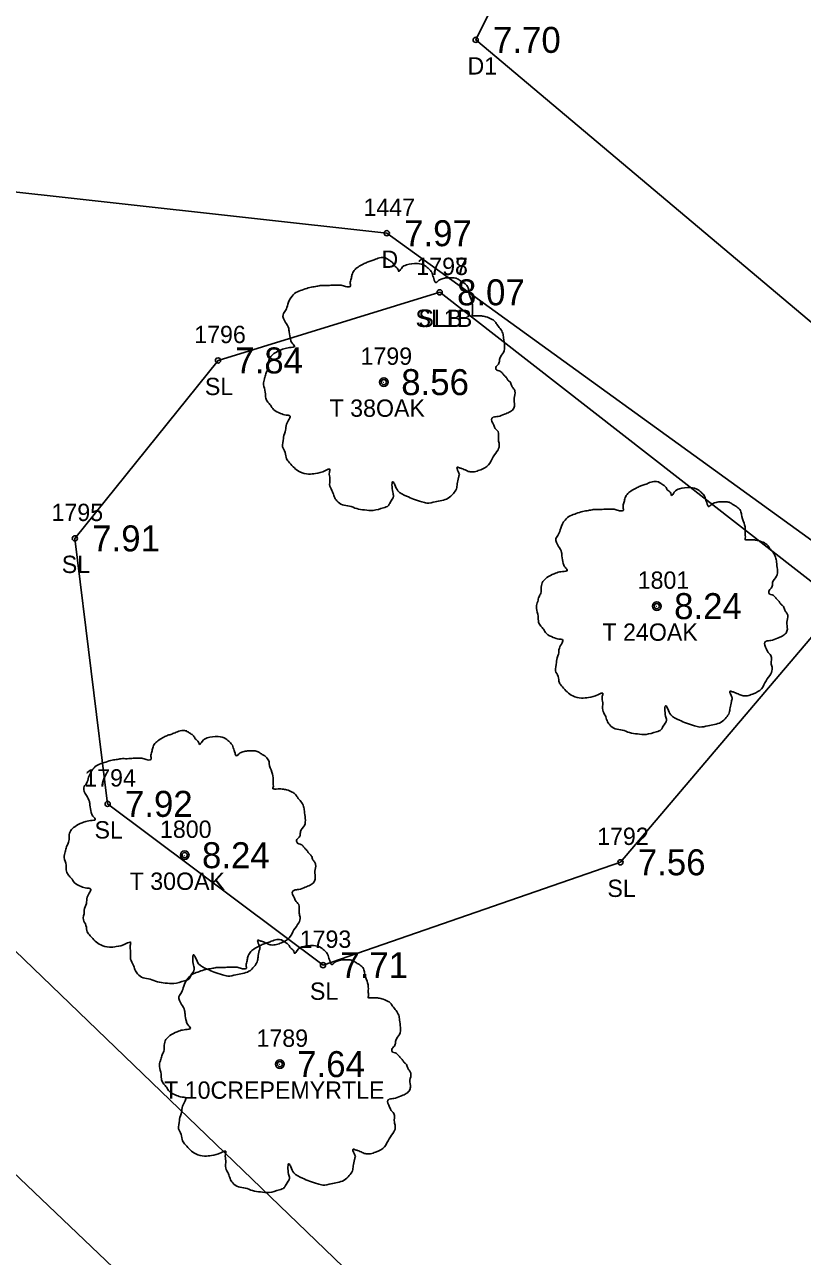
# Model space of a CAD drawing. Extents: x 2608598 to 2610682, y 641451 to 643526.
# Drawn here: x 2609134.2 to 2609179, y 643078.1 to 643149.1 of the extents above; entities that cross this region are included whole.
import ezdxf

# ---------------------------------------------------------------- set-up
doc = ezdxf.new("R2010")
doc.units = 0
for name, color, linetype in [('RD_EX_DR_Pipe', 7, 'Continuous'), ('RD_EX_Driveway', 7, 'Continuous'), ('RD_EX_Driveway_txCode', 7, 'Continuous'), ('RD_EX_Road', 7, 'Continuous'), ('RD_EX_TX_Driveway_ELEV', 7, 'Continuous'), ('RD_EX_TX_VEG_ELEV', 7, 'Continuous'), ('RD_EX_VEG', 7, 'Continuous'), ('RD_EX_VEG_txCode', 7, 'Continuous'), ('RD_SMD_Locator', 7, 'Continuous')]:
    doc.layers.add(name, color=color, linetype=linetype)

msp = doc.modelspace()

# ---------------------------------------------------------------- linework, layer by layer
at = {"layer": 'RD_EX_DR_Pipe'}
msp.add_line((2609069.044, 643157.849), (2609202.653, 643029.203), dxfattribs=at)
at = {"layer": 'RD_EX_Driveway'}
for points in [[(2609166.457, 643161.041), (2609160.17, 643148.257), (2609190.362, 643122.83), (2609213.317, 643102.873), (2609223.768, 643094.8), (2609208.755, 643077.174), (2609183.581, 643050.775)], [(2609100.57, 643145.923), (2609122.94, 643140.66), (2609155.044, 643137.099), (2609182.051, 643117.558), (2609202.041, 643097.354), (2609199.499, 643083.361), (2609176.116, 643060.669)]]:
    msp.add_lwpolyline(points, dxfattribs=at)
at = {"layer": 'RD_EX_Road'}
msp.add_lwpolyline([(2609042.495, 643170.94), (2609058.512, 643155.458), (2609096.06, 643119.372), (2609116.51, 643099.11), (2609162.396, 643055.351), (2609177.209, 643041.342), (2609188.353, 643030.959), (2609199.912, 643019.764), (2609205.803, 643014.044), (2609217.132, 643003.172), (2609235.835, 642983.899), (2609237.032, 642983.51), (2609256.803, 642965.042), (2609258.491, 642962.514), (2609263.653, 642957.664), (2609344.713, 642879.888)], dxfattribs=at)
at = {"layer": 'RD_EX_VEG'}
msp.add_line((2609181.166, 643115.711), (2609158.094, 643133.687), dxfattribs=at)
msp.add_lwpolyline([(2609181.166, 643115.711), (2609168.519, 643100.795), (2609151.366, 643094.858), (2609138.946, 643104.167), (2609137.057, 643119.488), (2609145.31, 643129.756), (2609158.094, 643133.687)], dxfattribs=at)
for centre, radius in [((2609154.878, 643128.504), 0.25), ((2609154.865, 643128.485), 0.0001), ((2609170.613, 643115.578), 0.25), ((2609170.6, 643115.559), 0.0001), ((2609143.388, 643101.204), 0.25), ((2609143.375, 643101.186), 0.0001), ((2609148.877, 643089.147), 0.25), ((2609148.864, 643089.128), 0.0001)]:
    msp.add_circle(centre, radius, dxfattribs=at)
for points in [[(2609155.01, 643135.671), (2609154.71, 643135.696), (2609154.385, 643135.596), (2609154.135, 643135.496), (2609153.91, 643135.421), (2609153.685, 643135.321), (2609153.386, 643135.147), (2609153.161, 643134.946), (2609153.036, 643134.697), (2609152.986, 643134.472), (2609152.936, 643134.197), (2609152.936, 643134.022), (2609152.811, 643133.997), (2609152.661, 643134.022), (2609152.411, 643134.097), (2609152.161, 643134.097), (2609151.911, 643134.097), (2609151.561, 643134.072), (2609151.211, 643134.072), (2609150.937, 643134.022), (2609150.612, 643133.972), (2609150.237, 643133.847), (2609149.887, 643133.722), (2609149.587, 643133.472), (2609149.337, 643132.997), (2609149.212, 643132.648), (2609149.062, 643132.398), (2609149.212, 643131.948), (2609149.387, 643131.598), (2609149.412, 643131.398), (2609149.487, 643130.973), (2609149.587, 643130.748), (2609149.712, 643130.548), (2609149.637, 643130.524), (2609149.262, 643130.473), (2609148.962, 643130.374), (2609148.538, 643130.149), (2609148.313, 643129.924), (2609148.213, 643129.599), (2609148.188, 643129.249), (2609148.088, 643129.049), (2609148.013, 643128.774), (2609147.988, 643128.699), (2609147.938, 643128.374), (2609148.038, 643127.925), (2609148.063, 643127.575), (2609148.188, 643127.35), (2609148.338, 643127.175), (2609148.513, 643126.925), (2609148.912, 643126.7), (2609149.237, 643126.6), (2609149.437, 643126.575), (2609149.262, 643126.075), (2609149.212, 643125.726), (2609149.087, 643125.326), (2609149.087, 643125.251), (2609149.037, 643124.776), (2609149.187, 643124.451), (2609149.262, 643124.076), (2609149.437, 643123.851), (2609149.712, 643123.552), (2609150.037, 643123.327), (2609150.537, 643123.202), (2609150.937, 643123.227), (2609151.511, 643123.402), (2609151.761, 643123.477), (2609151.736, 643123.302), (2609151.761, 643122.927), (2609151.761, 643122.502), (2609151.911, 643122.177), (2609152.011, 643121.902), (2609152.161, 643121.652), (2609152.486, 643121.427), (2609152.886, 643121.353), (2609153.311, 643121.203), (2609153.76, 643121.128), (2609154.26, 643121.103), (2609154.86, 643121.253), (2609155.135, 643121.378), (2609155.235, 643121.552), (2609155.435, 643121.927), (2609155.385, 643122.152), (2609155.41, 643122.752), (2609155.51, 643122.577), (2609155.685, 643122.227), (2609156.184, 643121.927), (2609156.584, 643121.752), (2609157.059, 643121.602), (2609157.359, 643121.527), (2609157.834, 643121.602), (2609158.208, 643121.677), (2609158.583, 643121.802), (2609158.883, 643122.077), (2609159.058, 643122.352), (2609159.108, 643122.627), (2609159.183, 643123.002), (2609159.233, 643123.177)], [(2609159.233, 643123.177), (2609159.158, 643123.352), (2609159.108, 643123.601), (2609159.183, 643123.576), (2609159.358, 643123.527), (2609159.633, 643123.402), (2609159.858, 643123.327), (2609160.183, 643123.352), (2609160.457, 643123.452), (2609160.907, 643123.726), (2609161.182, 643124.201), (2609161.457, 643124.601), (2609161.532, 643124.926), (2609161.482, 643125.151), (2609161.457, 643125.651), (2609161.257, 643125.9), (2609161.207, 643126.025), (2609161.107, 643126.425), (2609161.182, 643126.475), (2609161.457, 643126.525), (2609161.832, 643126.65), (2609162.107, 643126.775), (2609162.332, 643126.95), (2609162.407, 643127.175), (2609162.382, 643127.575), (2609162.432, 643127.975), (2609162.357, 643128.125), (2609162.257, 643128.274), (2609162.182, 643128.474), (2609162.032, 643128.624), (2609161.932, 643128.774), (2609161.832, 643128.874), (2609161.707, 643129.024), (2609161.532, 643129.149), (2609161.382, 643129.199), (2609161.332, 643129.349), (2609161.482, 643129.549), (2609161.532, 643129.649), (2609161.557, 643129.874), (2609161.782, 643130.224), (2609161.832, 643130.623), (2609161.782, 643131.048), (2609161.732, 643131.323), (2609161.582, 643131.598), (2609161.382, 643131.848), (2609161.257, 643132.023), (2609161.082, 643132.148), (2609160.757, 643132.273), (2609160.507, 643132.323), (2609160.158, 643132.323), (2609159.958, 643132.373), (2609159.983, 643132.423), (2609159.983, 643132.573), (2609159.983, 643132.848), (2609159.908, 643133.297), (2609159.758, 643133.797), (2609159.758, 643133.822), (2609159.658, 643134.072), (2609159.433, 643134.272), (2609159.258, 643134.372), (2609159.058, 643134.497), (2609158.808, 643134.522), (2609158.508, 643134.522), (2609158.233, 643134.472), (2609158.033, 643134.372), (2609157.859, 643134.247), (2609157.784, 643134.397), (2609157.684, 643134.697), (2609157.634, 643134.847), (2609157.484, 643135.022), (2609157.259, 643135.221), (2609156.809, 643135.346), (2609156.184, 643135.271), (2609155.884, 643135.071), (2609155.734, 643134.897), (2609155.685, 643135.022), (2609155.485, 643135.221), (2609155.385, 643135.396), (2609155.21, 643135.521), (2609155.06, 643135.621), (2609154.96, 643135.671)], [(2609170.745, 643122.745), (2609170.445, 643122.77), (2609170.12, 643122.67), (2609169.87, 643122.57), (2609169.645, 643122.495), (2609169.42, 643122.395), (2609169.121, 643122.221), (2609168.896, 643122.021), (2609168.771, 643121.771), (2609168.721, 643121.546), (2609168.671, 643121.271), (2609168.671, 643121.096), (2609168.546, 643121.071), (2609168.396, 643121.096), (2609168.146, 643121.171), (2609167.896, 643121.171), (2609167.646, 643121.171), (2609167.296, 643121.146), (2609166.946, 643121.146), (2609166.672, 643121.096), (2609166.347, 643121.046), (2609165.972, 643120.921), (2609165.622, 643120.796), (2609165.322, 643120.546), (2609165.072, 643120.072), (2609164.947, 643119.722), (2609164.797, 643119.472), (2609164.947, 643119.022), (2609165.122, 643118.672), (2609165.147, 643118.472), (2609165.222, 643118.047), (2609165.322, 643117.823), (2609165.447, 643117.623), (2609165.372, 643117.598), (2609164.997, 643117.548), (2609164.697, 643117.448), (2609164.273, 643117.223), (2609164.048, 643116.998), (2609163.948, 643116.673), (2609163.923, 643116.323), (2609163.823, 643116.123), (2609163.748, 643115.848), (2609163.723, 643115.773), (2609163.673, 643115.449), (2609163.773, 643114.999), (2609163.798, 643114.649), (2609163.923, 643114.424), (2609164.073, 643114.249), (2609164.248, 643113.999), (2609164.647, 643113.774), (2609164.972, 643113.674), (2609165.172, 643113.649), (2609164.997, 643113.15), (2609164.947, 643112.8), (2609164.822, 643112.4), (2609164.822, 643112.325), (2609164.772, 643111.85), (2609164.922, 643111.525), (2609164.997, 643111.15), (2609165.172, 643110.926), (2609165.447, 643110.626), (2609165.772, 643110.401), (2609166.272, 643110.276), (2609166.672, 643110.301), (2609167.246, 643110.476), (2609167.496, 643110.551), (2609167.471, 643110.376), (2609167.496, 643110.001), (2609167.496, 643109.576), (2609167.646, 643109.251), (2609167.746, 643108.976), (2609167.896, 643108.726), (2609168.221, 643108.502), (2609168.621, 643108.427), (2609169.046, 643108.277), (2609169.495, 643108.202), (2609169.995, 643108.177), (2609170.595, 643108.327), (2609170.87, 643108.452), (2609170.97, 643108.627), (2609171.17, 643109.001), (2609171.12, 643109.226), (2609171.145, 643109.826), (2609171.245, 643109.651), (2609171.42, 643109.301), (2609171.919, 643109.001), (2609172.319, 643108.826), (2609172.794, 643108.676), (2609173.094, 643108.602), (2609173.569, 643108.676), (2609173.943, 643108.751), (2609174.318, 643108.876), (2609174.618, 643109.151), (2609174.793, 643109.426), (2609174.843, 643109.701), (2609174.918, 643110.076), (2609174.968, 643110.251)], [(2609174.968, 643110.251), (2609174.893, 643110.426), (2609174.843, 643110.676), (2609174.918, 643110.651), (2609175.093, 643110.601), (2609175.368, 643110.476), (2609175.593, 643110.401), (2609175.918, 643110.426), (2609176.192, 643110.526), (2609176.642, 643110.801), (2609176.917, 643111.275), (2609177.192, 643111.675), (2609177.267, 643112), (2609177.217, 643112.225), (2609177.192, 643112.725), (2609176.992, 643112.975), (2609176.942, 643113.1), (2609176.842, 643113.499), (2609176.917, 643113.549), (2609177.192, 643113.599), (2609177.567, 643113.724), (2609177.842, 643113.849), (2609178.067, 643114.024), (2609178.142, 643114.249), (2609178.117, 643114.649), (2609178.167, 643115.049), (2609178.092, 643115.199), (2609177.992, 643115.349), (2609177.917, 643115.549), (2609177.767, 643115.698), (2609177.667, 643115.848), (2609177.567, 643115.948), (2609177.442, 643116.098), (2609177.267, 643116.223), (2609177.117, 643116.273), (2609177.067, 643116.423), (2609177.217, 643116.623), (2609177.267, 643116.723), (2609177.292, 643116.948), (2609177.517, 643117.298), (2609177.567, 643117.698), (2609177.517, 643118.122), (2609177.467, 643118.397), (2609177.317, 643118.672), (2609177.117, 643118.922), (2609176.992, 643119.097), (2609176.817, 643119.222), (2609176.492, 643119.347), (2609176.242, 643119.397), (2609175.893, 643119.397), (2609175.693, 643119.447), (2609175.718, 643119.497), (2609175.718, 643119.647), (2609175.718, 643119.922), (2609175.643, 643120.371), (2609175.493, 643120.871), (2609175.493, 643120.896), (2609175.393, 643121.146), (2609175.168, 643121.346), (2609174.993, 643121.446), (2609174.793, 643121.571), (2609174.543, 643121.596), (2609174.243, 643121.596), (2609173.968, 643121.546), (2609173.768, 643121.446), (2609173.594, 643121.321), (2609173.519, 643121.471), (2609173.419, 643121.771), (2609173.369, 643121.921), (2609173.219, 643122.096), (2609172.994, 643122.296), (2609172.544, 643122.42), (2609171.919, 643122.346), (2609171.619, 643122.146), (2609171.469, 643121.971), (2609171.42, 643122.096), (2609171.22, 643122.296), (2609171.12, 643122.47), (2609170.945, 643122.595), (2609170.795, 643122.695), (2609170.695, 643122.745)], [(2609143.52, 643108.372), (2609143.22, 643108.397), (2609142.895, 643108.297), (2609142.645, 643108.197), (2609142.42, 643108.122), (2609142.195, 643108.022), (2609141.896, 643107.847), (2609141.671, 643107.647), (2609141.546, 643107.397), (2609141.496, 643107.172), (2609141.446, 643106.897), (2609141.446, 643106.722), (2609141.321, 643106.697), (2609141.171, 643106.722), (2609140.921, 643106.797), (2609140.671, 643106.797), (2609140.421, 643106.797), (2609140.071, 643106.772), (2609139.722, 643106.772), (2609139.447, 643106.722), (2609139.122, 643106.672), (2609138.747, 643106.547), (2609138.397, 643106.422), (2609138.097, 643106.173), (2609137.847, 643105.698), (2609137.722, 643105.348), (2609137.573, 643105.098), (2609137.722, 643104.648), (2609137.897, 643104.298), (2609137.922, 643104.098), (2609137.997, 643103.674), (2609138.097, 643103.449), (2609138.222, 643103.249), (2609138.147, 643103.224), (2609137.772, 643103.174), (2609137.473, 643103.074), (2609137.048, 643102.849), (2609136.823, 643102.624), (2609136.723, 643102.299), (2609136.698, 643101.949), (2609136.598, 643101.75), (2609136.523, 643101.475), (2609136.498, 643101.4), (2609136.448, 643101.075), (2609136.548, 643100.625), (2609136.573, 643100.275), (2609136.698, 643100.05), (2609136.848, 643099.875), (2609137.023, 643099.625), (2609137.423, 643099.401), (2609137.747, 643099.301), (2609137.947, 643099.276), (2609137.772, 643098.776), (2609137.722, 643098.426), (2609137.598, 643098.026), (2609137.598, 643097.951), (2609137.548, 643097.476), (2609137.697, 643097.151), (2609137.772, 643096.777), (2609137.947, 643096.552), (2609138.222, 643096.252), (2609138.547, 643096.027), (2609139.047, 643095.902), (2609139.447, 643095.927), (2609140.021, 643096.102), (2609140.271, 643096.177), (2609140.246, 643096.002), (2609140.271, 643095.627), (2609140.271, 643095.202), (2609140.421, 643094.878), (2609140.521, 643094.603), (2609140.671, 643094.353), (2609140.996, 643094.128), (2609141.396, 643094.053), (2609141.821, 643093.903), (2609142.271, 643093.828), (2609142.77, 643093.803), (2609143.37, 643093.953), (2609143.645, 643094.078), (2609143.745, 643094.253), (2609143.945, 643094.628), (2609143.895, 643094.853), (2609143.92, 643095.452), (2609144.02, 643095.277), (2609144.195, 643094.927), (2609144.694, 643094.628), (2609145.094, 643094.453), (2609145.569, 643094.303), (2609145.869, 643094.228), (2609146.344, 643094.303), (2609146.719, 643094.378), (2609147.093, 643094.503), (2609147.393, 643094.778), (2609147.568, 643095.052), (2609147.618, 643095.327), (2609147.693, 643095.702), (2609147.743, 643095.877)], [(2609147.743, 643095.877), (2609147.668, 643096.052), (2609147.618, 643096.302), (2609147.693, 643096.277), (2609147.868, 643096.227), (2609148.143, 643096.102), (2609148.368, 643096.027), (2609148.693, 643096.052), (2609148.968, 643096.152), (2609149.417, 643096.427), (2609149.692, 643096.902), (2609149.967, 643097.301), (2609150.042, 643097.626), (2609149.992, 643097.851), (2609149.967, 643098.351), (2609149.767, 643098.601), (2609149.717, 643098.726), (2609149.617, 643099.126), (2609149.692, 643099.176), (2609149.967, 643099.226), (2609150.342, 643099.351), (2609150.617, 643099.475), (2609150.842, 643099.65), (2609150.917, 643099.875), (2609150.892, 643100.275), (2609150.942, 643100.675), (2609150.867, 643100.825), (2609150.767, 643100.975), (2609150.692, 643101.175), (2609150.542, 643101.325), (2609150.442, 643101.475), (2609150.342, 643101.575), (2609150.217, 643101.725), (2609150.042, 643101.849), (2609149.892, 643101.899), (2609149.842, 643102.049), (2609149.992, 643102.249), (2609150.042, 643102.349), (2609150.067, 643102.574), (2609150.292, 643102.924), (2609150.342, 643103.324), (2609150.292, 643103.749), (2609150.242, 643104.024), (2609150.092, 643104.298), (2609149.892, 643104.548), (2609149.767, 643104.723), (2609149.592, 643104.848), (2609149.267, 643104.973), (2609149.018, 643105.023), (2609148.668, 643105.023), (2609148.468, 643105.073), (2609148.493, 643105.123), (2609148.493, 643105.273), (2609148.493, 643105.548), (2609148.418, 643105.998), (2609148.268, 643106.497), (2609148.268, 643106.522), (2609148.168, 643106.772), (2609147.943, 643106.972), (2609147.768, 643107.072), (2609147.568, 643107.197), (2609147.318, 643107.222), (2609147.018, 643107.222), (2609146.743, 643107.172), (2609146.544, 643107.072), (2609146.369, 643106.947), (2609146.294, 643107.097), (2609146.194, 643107.397), (2609146.144, 643107.547), (2609145.994, 643107.722), (2609145.769, 643107.922), (2609145.319, 643108.047), (2609144.694, 643107.972), (2609144.394, 643107.772), (2609144.245, 643107.597), (2609144.195, 643107.722), (2609143.995, 643107.922), (2609143.895, 643108.097), (2609143.72, 643108.222), (2609143.57, 643108.322), (2609143.47, 643108.372)], [(2609149.008, 643096.314), (2609148.709, 643096.339), (2609148.384, 643096.239), (2609148.134, 643096.139), (2609147.909, 643096.064), (2609147.684, 643095.964), (2609147.384, 643095.789), (2609147.159, 643095.589), (2609147.034, 643095.339), (2609146.984, 643095.114), (2609146.934, 643094.839), (2609146.934, 643094.664), (2609146.809, 643094.639), (2609146.659, 643094.664), (2609146.41, 643094.739), (2609146.16, 643094.739), (2609145.91, 643094.739), (2609145.56, 643094.714), (2609145.21, 643094.714), (2609144.935, 643094.664), (2609144.61, 643094.615), (2609144.235, 643094.49), (2609143.886, 643094.365), (2609143.586, 643094.115), (2609143.336, 643093.64), (2609143.211, 643093.29), (2609143.061, 643093.04), (2609143.211, 643092.59), (2609143.386, 643092.241), (2609143.411, 643092.041), (2609143.486, 643091.616), (2609143.586, 643091.391), (2609143.711, 643091.191), (2609143.636, 643091.166), (2609143.261, 643091.116), (2609142.961, 643091.016), (2609142.536, 643090.791), (2609142.311, 643090.566), (2609142.211, 643090.241), (2609142.186, 643089.892), (2609142.087, 643089.692), (2609142.012, 643089.417), (2609141.987, 643089.342), (2609141.936, 643089.017), (2609142.036, 643088.567), (2609142.061, 643088.217), (2609142.186, 643087.992), (2609142.336, 643087.818), (2609142.511, 643087.568), (2609142.911, 643087.343), (2609143.236, 643087.243), (2609143.436, 643087.218), (2609143.261, 643086.718), (2609143.211, 643086.368), (2609143.086, 643085.968), (2609143.086, 643085.893), (2609143.036, 643085.419), (2609143.186, 643085.094), (2609143.261, 643084.719), (2609143.436, 643084.494), (2609143.711, 643084.194), (2609144.036, 643083.969), (2609144.535, 643083.844), (2609144.935, 643083.869), (2609145.51, 643084.044), (2609145.76, 643084.119), (2609145.735, 643083.944), (2609145.76, 643083.569), (2609145.76, 643083.145), (2609145.91, 643082.82), (2609146.01, 643082.545), (2609146.16, 643082.295), (2609146.485, 643082.07), (2609146.884, 643081.995), (2609147.309, 643081.845), (2609147.759, 643081.77), (2609148.259, 643081.745), (2609148.859, 643081.895), (2609149.133, 643082.02), (2609149.233, 643082.195), (2609149.433, 643082.57), (2609149.383, 643082.795), (2609149.408, 643083.394), (2609149.508, 643083.219), (2609149.683, 643082.87), (2609150.183, 643082.57), (2609150.583, 643082.395), (2609151.058, 643082.245), (2609151.357, 643082.17), (2609151.832, 643082.245), (2609152.207, 643082.32), (2609152.582, 643082.445), (2609152.882, 643082.72), (2609153.057, 643082.995), (2609153.107, 643083.269), (2609153.182, 643083.644), (2609153.232, 643083.819)], [(2609153.232, 643083.819), (2609153.157, 643083.994), (2609153.107, 643084.244), (2609153.182, 643084.219), (2609153.357, 643084.169), (2609153.631, 643084.044), (2609153.856, 643083.969), (2609154.181, 643083.994), (2609154.456, 643084.094), (2609154.906, 643084.369), (2609155.181, 643084.844), (2609155.456, 643085.244), (2609155.531, 643085.568), (2609155.481, 643085.793), (2609155.456, 643086.293), (2609155.256, 643086.543), (2609155.206, 643086.668), (2609155.106, 643087.068), (2609155.181, 643087.118), (2609155.456, 643087.168), (2609155.83, 643087.293), (2609156.105, 643087.418), (2609156.33, 643087.593), (2609156.405, 643087.818), (2609156.38, 643088.217), (2609156.43, 643088.617), (2609156.355, 643088.767), (2609156.255, 643088.917), (2609156.18, 643089.117), (2609156.03, 643089.267), (2609155.93, 643089.417), (2609155.83, 643089.517), (2609155.706, 643089.667), (2609155.531, 643089.792), (2609155.381, 643089.842), (2609155.331, 643089.992), (2609155.481, 643090.191), (2609155.531, 643090.291), (2609155.556, 643090.516), (2609155.78, 643090.866), (2609155.83, 643091.266), (2609155.78, 643091.691), (2609155.731, 643091.966), (2609155.581, 643092.241), (2609155.381, 643092.49), (2609155.256, 643092.665), (2609155.081, 643092.79), (2609154.756, 643092.915), (2609154.506, 643092.965), (2609154.156, 643092.965), (2609153.956, 643093.015), (2609153.981, 643093.065), (2609153.981, 643093.215), (2609153.981, 643093.49), (2609153.906, 643093.94), (2609153.756, 643094.44), (2609153.756, 643094.465), (2609153.656, 643094.714), (2609153.431, 643094.914), (2609153.257, 643095.014), (2609153.057, 643095.139), (2609152.807, 643095.164), (2609152.507, 643095.164), (2609152.232, 643095.114), (2609152.032, 643095.014), (2609151.857, 643094.889), (2609151.782, 643095.039), (2609151.682, 643095.339), (2609151.632, 643095.489), (2609151.482, 643095.664), (2609151.257, 643095.864), (2609150.808, 643095.989), (2609150.183, 643095.914), (2609149.883, 643095.714), (2609149.733, 643095.539), (2609149.683, 643095.664), (2609149.483, 643095.864), (2609149.383, 643096.039), (2609149.208, 643096.164), (2609149.058, 643096.264), (2609148.958, 643096.314)]]:
    msp.add_spline(points, degree=3, dxfattribs=at)
at = {"layer": 'RD_SMD_Locator'}
for centre in [(2609160.17, 643148.257), (2609155.044, 643137.099), (2609158.094, 643133.687), (2609158.094, 643133.687), (2609145.31, 643129.756), (2609154.878, 643128.504), (2609137.057, 643119.488), (2609170.613, 643115.578), (2609138.946, 643104.167), (2609143.388, 643101.204), (2609168.519, 643100.795), (2609151.366, 643094.858), (2609148.877, 643089.147)]:
    msp.add_circle(centre, 0.15, dxfattribs=at)

# ---------------------------------------------------------------- texts
at = {"layer": 'RD_EX_Driveway_txCode'}
for s, p in [('D1', (2609159.698, 643146.257)), ('1447', (2609153.698, 643138.099)), ('D', (2609154.737, 643135.099))]:
    msp.add_text(s, height=1, dxfattribs=at).set_placement(p)
at = {"layer": 'RD_EX_TX_Driveway_ELEV'}
for s, p in [('7.70', (2609161.17, 643147.507)), ('7.97', (2609156.044, 643136.349))]:
    msp.add_text(s, height=1.5, dxfattribs=at).set_placement(p)
at = {"layer": 'RD_EX_TX_VEG_ELEV'}
for s, p in [('8.07', (2609159.094, 643132.937)), ('8.07', (2609159.094, 643132.937)), ('7.84', (2609146.31, 643129.006)), ('8.56', (2609155.878, 643127.754)), ('7.91', (2609138.057, 643118.738)), ('8.24', (2609171.613, 643114.828)), ('7.92', (2609139.946, 643103.417)), ('8.24', (2609144.388, 643100.454)), ('7.56', (2609169.519, 643100.045)), ('7.71', (2609152.366, 643094.108)), ('7.64', (2609149.877, 643088.397))]:
    msp.add_text(s, height=1.5, dxfattribs=at).set_placement(p)
at = {"layer": 'RD_EX_VEG_txCode'}
for s, p in [('1797', (2609156.747, 643134.687)), ('1798', (2609156.747, 643134.687)), ('SL1B', (2609156.7, 643131.687)), ('SLB', (2609156.865, 643131.687)), ('1796', (2609143.939, 643130.756)), ('1799', (2609153.531, 643129.504)), ('SL', (2609144.554, 643127.756)), ('T 38OAK', (2609151.744, 643126.504)), ('1795', (2609135.71, 643120.488)), ('SL', (2609136.301, 643117.488)), ('1801', (2609169.511, 643116.578)), ('T 24OAK', (2609167.479, 643113.578)), ('1794', (2609137.599, 643105.167)), ('SL', (2609138.19, 643102.167)), ('1800', (2609141.963, 643102.204)), ('1792', (2609167.172, 643101.795)), ('T 30OAK', (2609140.215, 643099.204)), ('SL', (2609167.763, 643098.795)), ('1793', (2609150.02, 643095.858)), ('SL', (2609150.61, 643092.858)), ('1789', (2609147.53, 643090.147)), ('T 10CREPEMYRTLE', (2609142.203, 643087.147))]:
    msp.add_text(s, height=1, dxfattribs=at).set_placement(p)

doc.saveas('drawing.dxf')
